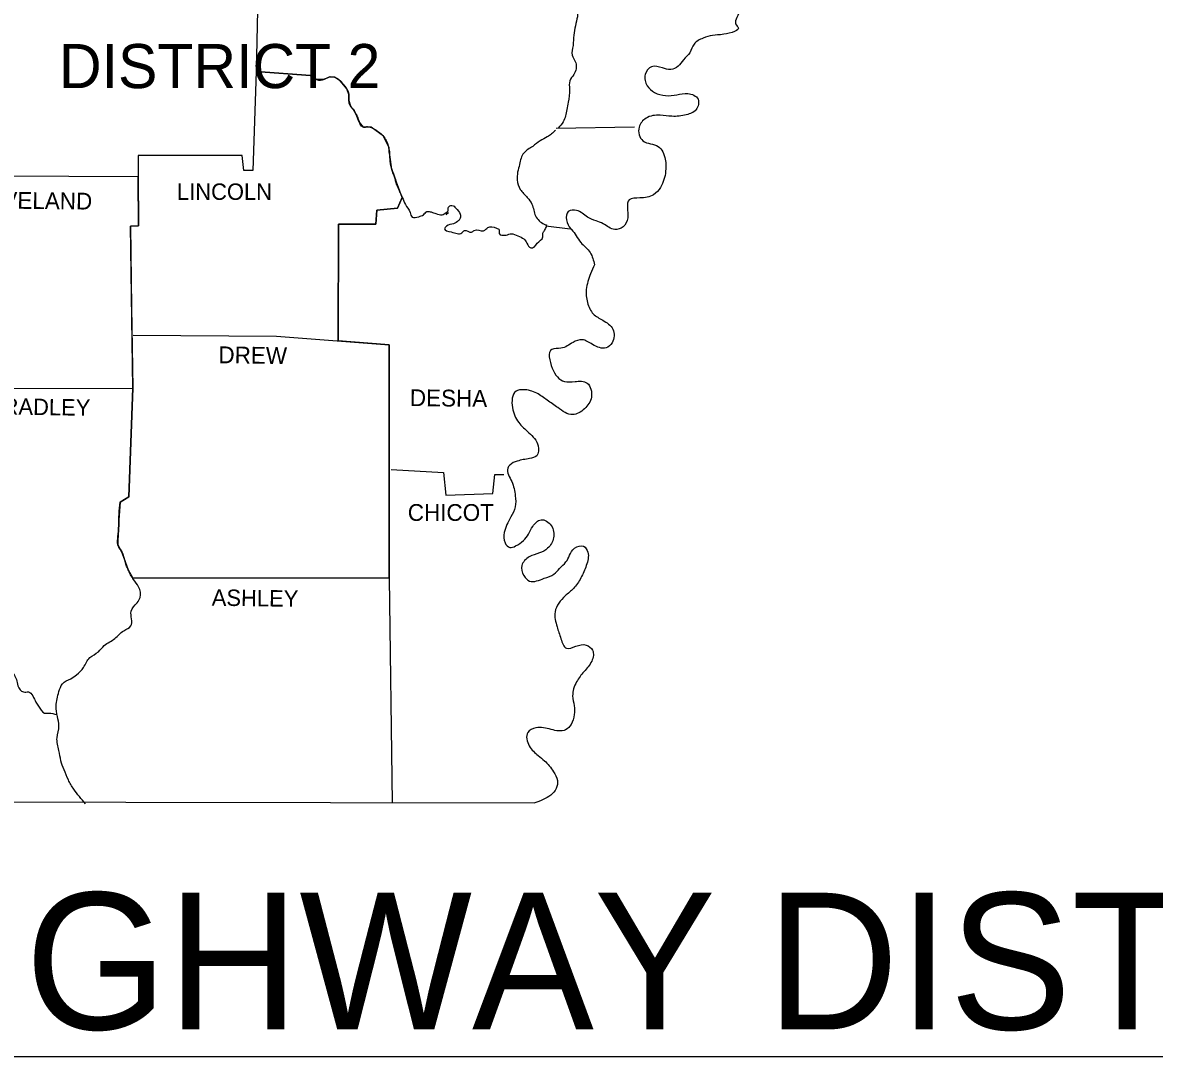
# Model space of a CAD drawing. Extents: x -33639 to 34530, y -17264 to 5867.
# Drawn here: x -16002 to -14408, y -10461 to -9004 of the extents above; entities that cross this region are included whole.
import ezdxf

# ---------------------------------------------------------------- set-up
doc = ezdxf.new("R2010")
doc.units = 0
for name, color, linetype in [('1', 7, 'Continuous'), ('2', 7, 'Continuous'), ('3', 7, 'Continuous'), ('S_MISC_BOUNDARY', 7, 'Continuous')]:
    doc.layers.add(name, color=color, linetype=linetype)

msp = doc.modelspace()

# ---------------------------------------------------------------- linework, layer by layer
at = {"layer": '1'}
for p, q in [((-15250.6, -9152.5), (-15140.6, -9150.8)), ((-17741.9, -10460.7), (-14228.8, -10460.7))]:
    msp.add_line(p, q, dxfattribs=at)
for points in [[(-15668.9, -8856.7), (-15673.3, -9072.7), (-15596.8, -9078.7)], [(-15673.3, -9072.7), (-15678.3, -9212.5), (-15690.9, -9212.5), (-15693.1, -9191), (-15839.5, -9191), (-15839.5, -9219.4)], [(-15467.5, -9250.4), (-15474.1, -9265.3), (-15503.3, -9268.1), (-15504.9, -9287.9), (-15557.2, -9287.9), (-15557.7, -9452.4)], [(-15405.8, -9274.7), (-15404.2, -9273), (-15402.5, -9271.4), (-15402.5, -9271.4)], [(-15846.9, -9444.2), (-15644.7, -9445.8), (-15486.2, -9457.9)], [(-15486.2, -9457.9), (-15486.2, -9787), (-15481.8, -10103.5)], [(-16096, -9519.6), (-15847.2, -9519)], [(-15483.4, -9633.5), (-15409.7, -9637.9), (-15406.4, -9669.8), (-15339.8, -9667.6), (-15337.1, -9640.6), (-15324.4, -9640.6)], [(-17299.1, -9655), (-17298, -10100.2), (-15280.9, -10103.5)], [(-15847.4, -9786.5), (-15486.2, -9786.5)]]:
    msp.add_lwpolyline(points, dxfattribs=at)
for points in [[(-14817.5, -8617), (-14830.2, -8632.9), (-14848.9, -8623), (-14848.9, -8609.8), (-14846.1, -8596.1), (-14852.7, -8587.3), (-14864.3, -8591.1), (-14864.3, -8608.2), (-14865.4, -8624.7), (-14868.7, -8648.4), (-14861, -8655.5), (-14843.4, -8657.7), (-14830.7, -8661), (-14823, -8673.7), (-14823.6, -8689.1), (-14829.6, -8703.9), (-14838.4, -8716), (-14852.2, -8720.5), (-14863.2, -8713.3), (-14867.6, -8699), (-14872.6, -8686.3), (-14881.9, -8677), (-14891.8, -8687.4), (-14894, -8706.7), (-14893.5, -8723.2), (-14893.5, -8745.8), (-14879.2, -8760.6), (-14870.4, -8777.7), (-14873.1, -8793.1), (-14883.6, -8811.3), (-14888, -8827.2), (-14892.4, -8848.7), (-14891.8, -8872.3), (-14895.7, -8895.5), (-14903.4, -8910.9), (-14917.7, -8923.5), (-14927, -8931.8), (-14934.7, -8940), (-14938.6, -8956.6), (-14941.3, -8968.1), (-14951.8, -8981.9), (-14960.1, -8983), (-14966.7, -8977.5), (-14968.9, -8968.1), (-14968.9, -8958.8), (-14973.3, -8949.4), (-14987, -8945.5), (-14998, -8946.1), (-15003, -8953.8), (-14995.8, -8975.3), (-14993.1, -8989), (-14996.9, -9007.7), (-14994.7, -9009.9), (-15014.5, -9020.4), (-15030.5, -9022), (-15043.7, -9025.9), (-15056.4, -9034.2), (-15062.4, -9046.3), (-15071.2, -9056.2), (-15078.9, -9065.5), (-15089.4, -9069.9), (-15101, -9067.7), (-15116.4, -9066.1), (-15125.2, -9077.1), (-15122.4, -9093), (-15112, -9102.4), (-15096.5, -9106.8), (-15080.6, -9105.7), (-15065.2, -9104), (-15050.9, -9111.8), (-15053.6, -9126.6), (-15067.4, -9133.8), (-15087.7, -9136), (-15104.3, -9134.3), (-15124.1, -9138.7), (-15134, -9151.4), (-15128.5, -9170.6), (-15107, -9178.3), (-15097.1, -9196.5), (-15096.5, -9213.6), (-15103.7, -9236.1), (-15113.6, -9246.6), (-15132.9, -9251), (-15147.7, -9253.7), (-15149.9, -9279.1), (-15156.5, -9291.7), (-15168.1, -9295.6), (-15184.6, -9287.3), (-15194.5, -9283.5), (-15206.6, -9278), (-15222, -9268.6), (-15233.6, -9270.3), (-15230.3, -9294.5), (-15229.2, -9295.6), (-15216, -9313.7), (-15202.8, -9328), (-15196.7, -9345.1)], [(-15596.8, -9078.7), (-15588.6, -9084.2), (-15577, -9083.7), (-15569.3, -9080.4), (-15563.2, -9080.9), (-15555, -9085.9), (-15549.5, -9092.5), (-15545.6, -9097.4), (-15542.9, -9105.1), (-15542.9, -9112.3), (-15540.1, -9122.2), (-15536.8, -9126.1), (-15532.4, -9133.2), (-15529.7, -9139.8), (-15528, -9144.2), (-15522, -9151.4), (-15516.5, -9150.8), (-15511.5, -9151.4), (-15504.9, -9155.2), (-15495, -9162.9), (-15493.4, -9165.1), (-15486.7, -9179.4), (-15485.6, -9188.3), (-15484.5, -9199.8), (-15482.3, -9210.8), (-15477.9, -9222.9), (-15475.7, -9231.2), (-15470.8, -9242.7), (-15467.5, -9250.4), (-15463.1, -9260.3), (-15456.5, -9271.4), (-15453.7, -9278), (-15444.4, -9277.4), (-15437.8, -9274.7), (-15432.8, -9270.3), (-15426.8, -9270.8), (-15420.2, -9273), (-15411.4, -9274.7), (-15405.8, -9271.4), (-15403.1, -9269.2), (-15402.5, -9264.2), (-15397.6, -9261.5), (-15392.1, -9265.3), (-15386, -9274.1), (-15386, -9279.6), (-15388.2, -9282.9), (-15395.4, -9287.3), (-15405.3, -9290.6), (-15408, -9294.5), (-15398.7, -9298.9), (-15383.8, -9300), (-15380, -9296.7), (-15370.1, -9299.4), (-15366.2, -9296.7), (-15353, -9297.2), (-15347, -9292.8), (-15334.9, -9293.4), (-15331, -9296.1), (-15331, -9301.1), (-15321.1, -9303.3), (-15313.9, -9301.6), (-15304.6, -9304.4), (-15296.3, -9308.8), (-15291.9, -9314.8), (-15286.4, -9321.4), (-15281.5, -9319.8), (-15277.6, -9314.8), (-15269.4, -9306), (-15269.4, -9300.5), (-15267.2, -9296.7), (-15264.4, -9291.2)], [(-15196.7, -9345.1), (-15202.2, -9357.8), (-15208.3, -9379.8), (-15206.6, -9398.5), (-15198.4, -9414.4), (-15185.2, -9423.3), (-15170.8, -9435.9), (-15171.9, -9455.2), (-15180.2, -9462.3), (-15199.5, -9457.4), (-15214.3, -9450.8), (-15227, -9454.6), (-15244, -9462.9), (-15256.7, -9464.5), (-15256.2, -9490.9), (-15239.1, -9509.7), (-15224.2, -9509.7), (-15207.2, -9511.9), (-15201.1, -9531.7), (-15211, -9548.2), (-15227.5, -9556.4), (-15248.4, -9546.5), (-15263.3, -9536.1), (-15278.2, -9526.2), (-15296.9, -9521.2), (-15307.3, -9523.4), (-15312.3, -9546.5), (-15303.5, -9567.4), (-15289.2, -9581.8), (-15276, -9600.5), (-15278.2, -9614.2), (-15288.1, -9618.1), (-15305.7, -9621.9), (-15316.1, -9627.4), (-15318.9, -9631.8), (-15313.4, -9650.6), (-15308.4, -9670.9), (-15308.4, -9686.3), (-15314.5, -9700.6), (-15323.8, -9722.6), (-15322.7, -9737), (-15316.1, -9743.6), (-15307.9, -9741.4), (-15296.9, -9733.7), (-15289.7, -9724.8), (-15283.7, -9713.8), (-15272.1, -9704.5), (-15257.8, -9712.7), (-15254.5, -9729.8), (-15262.8, -9744.7), (-15274.3, -9751.3), (-15288.6, -9756.8), (-15299.1, -9768.9), (-15296.3, -9783.2), (-15288.1, -9790.9), (-15267.7, -9787), (-15253.9, -9781), (-15246.2, -9773.3), (-15236.9, -9763.9), (-15231.9, -9754.6), (-15224.8, -9744.7), (-15212.1, -9741.9), (-15206.1, -9750.2), (-15208.3, -9768.9), (-15216, -9786.5), (-15226.4, -9801.3), (-15238, -9811.8), (-15252.3, -9834.4), (-15249.5, -9855.3), (-15244, -9872.3), (-15236.3, -9885.6), (-15223.1, -9882.8), (-15208.3, -9881.1), (-15199.5, -9888.3), (-15200.6, -9903.7), (-15211.6, -9918.6), (-15222, -9932.9), (-15227.5, -9952.7), (-15225.3, -9966.5), (-15225.3, -9979.1), (-15229.7, -9992.9), (-15237.4, -10000.6), (-15257.8, -10000), (-15279.3, -9997.8), (-15290.8, -10004.4), (-15288.6, -10023.1), (-15276, -10036.9), (-15267.2, -10044.1), (-15254.5, -10059.5), (-15249, -10072.1), (-15250.6, -10083.1), (-15258.4, -10092.5), (-15280.9, -10103.5)], [(-16413.5, -9806.9), (-16404.7, -9800.8), (-16396.5, -9797.5), (-16388.2, -9799.1), (-16379.4, -9800.2), (-16371.7, -9799.1), (-16361.8, -9800.8), (-16353.6, -9805.8), (-16344.2, -9809.6), (-16334.8, -9809.6), (-16326.6, -9809.6), (-16319.4, -9814.6), (-16306.2, -9814), (-16295.2, -9809.6), (-16284.2, -9806.3), (-16269.4, -9804.6), (-16256.1, -9814), (-16246.8, -9821.7), (-16239.1, -9830.5), (-16233.6, -9840.4), (-16227.5, -9845.9), (-16217.6, -9849.8), (-16209.9, -9851.4), (-16200.6, -9854.2), (-16195.6, -9856.4), (-16191.2, -9866.8), (-16184, -9881.1), (-16170.3, -9886.1), (-16153.2, -9879.5), (-16139.5, -9875.6), (-16129.6, -9872.3), (-16123.5, -9870.1), (-16118, -9869.6), (-16119.7, -9868.5), (-16113.1, -9866.8), (-16107, -9871.2), (-16103.1, -9877.3), (-16096.5, -9886.1), (-16090.5, -9893.8), (-16084.4, -9896.6), (-16078.4, -9893.3), (-16070.1, -9896), (-16063, -9898.8), (-16054.7, -9901), (-16047.6, -9901.5), (-16038.2, -9903.7), (-16031, -9907.6), (-16024.4, -9911.4), (-16017.8, -9918.6), (-16011.2, -9929.6), (-16009, -9938.4), (-16001.3, -9947.2), (-15994.2, -9947.2), (-15983.7, -9961.5), (-15979.9, -9967), (-15971.6, -9976.9), (-15965.6, -9976.9), (-15954, -9979.1)]]:
    msp.add_spline(points, degree=3, dxfattribs=at)
at = {"layer": 'S_MISC_BOUNDARY'}
for p, q in [((-15569.4, -9080.4), (-15573.5, -9082.2)), ((-15693.1, -9191), (-15839.5, -9191)), ((-15690.9, -9212.5), (-15693.1, -9191)), ((-15678.3, -9212.5), (-15690.9, -9212.5)), ((-15839, -9290.1), (-15850.5, -9290.6)), ((-15850.5, -9290.6), (-15848.9, -9404.8)), ((-15265.5, -9290.1), (-15230.8, -9294.5)), ((-15486.2, -9457.9), (-15557.7, -9452.5)), ((-15850, -9595.5), (-15852.7, -9672)), ((-15852.7, -9672), (-15864.8, -9679.7))]:
    msp.add_line(p, q, dxfattribs=at)
for points in [[(-15839.5, -9191), (-15839.5, -9219.4), (-15839, -9290.1), (-15850.5, -9290.6), (-15848.9, -9404.8), (-15847.2, -9519), (-15850, -9595.5), (-15852.7, -9672), (-15864.8, -9679.7), (-15866.8, -9704.8), (-15868.1, -9733.9), (-15868.1, -9739.7), (-15864.8, -9746), (-15862.9, -9749.7), (-15857.7, -9764.5), (-15855.8, -9769.7), (-15853.8, -9774.9), (-15850, -9781.8), (-15847.3, -9786.6), (-15666.8, -9786.5), (-15486.2, -9787), (-15486.2, -9457.9), (-15557.7, -9452.4), (-15557.2, -9287.9), (-15504.9, -9287.9), (-15503.3, -9268.1), (-15474.1, -9265.3), (-15467.5, -9250.4), (-15482.3, -9210.8), (-15486.7, -9179.4), (-15494.2, -9164), (-15511.5, -9151.4), (-15516.5, -9150.8), (-15522, -9151.4), (-15528, -9144.2), (-15532.4, -9133.2), (-15536.8, -9126.1), (-15540.1, -9122.2), (-15542.9, -9112.3), (-15542.9, -9105.1), (-15545.6, -9097.4), (-15555, -9085.9), (-15563.1, -9081), (-15569.3, -9080.3), (-15577.1, -9083.7), (-15588.5, -9084.2), (-15596.9, -9078.7), (-15673.3, -9072.7), (-15678.3, -9212.5), (-15690.9, -9212.5), (-15693.1, -9191), (-15839.5, -9191)], [(-15596.8, -9078.7), (-15673.3, -9072.7), (-15678.3, -9212.5)], [(-15555, -9085.8), (-15563.1, -9081), (-15569.2, -9080.4)], [(-15542.9, -9109.2), (-15542.9, -9105.1), (-15545.6, -9097.4), (-15554.7, -9086.2)], [(-15528.1, -9144), (-15532.4, -9133.2), (-15536.8, -9126.1), (-15538.1, -9124.6)], [(-15486.1, -9184), (-15486.7, -9179.4), (-15494.2, -9164), (-15511.5, -9151.4), (-15516.5, -9150.8), (-15517.8, -9151)], [(-15839.5, -9191), (-15839.5, -9219.4), (-15839.5, -9221.3), (-15839, -9290.1)], [(-15864.8, -9679.7), (-15852.7, -9672), (-15847.2, -9519), (-15850.5, -9290.6), (-15839, -9290.1), (-15839.5, -9221.3), (-15839.5, -9221.3), (-16035.5, -9220.2), (-16115.8, -9225.1)], [(-15557.7, -9452.4), (-15557.2, -9287.9), (-15504.9, -9287.9), (-15503.3, -9268.1), (-15474.1, -9265.3), (-15467.5, -9250.4)], [(-15848.9, -9404.8), (-15847.2, -9519), (-15850, -9595.5)], [(-15557.7, -9452.5), (-15557.7, -9452.4)], [(-15857.7, -9764.5), (-15855.8, -9769.7), (-15853.8, -9774.9), (-15850, -9781.8), (-15847.4, -9786.5), (-15666.8, -9786.5), (-15486.2, -9787), (-15486.2, -9457.9)], [(-15864.8, -9679.7), (-15866.8, -9704.8), (-15866.8, -9705.8)], [(-15867.4, -9718.5), (-15868.1, -9733.9), (-15868.1, -9739.7), (-15864.8, -9746), (-15863.7, -9748.3)]]:
    msp.add_lwpolyline(points, dxfattribs=at)
for points in [[(-15387.7, -8794.2), (-15386, -8816.8), (-15372.8, -8820.1), (-15367.3, -8826.1), (-15364.6, -8838.8), (-15355.2, -8844.3), (-15342.6, -8852), (-15334.9, -8857.5), (-15329.3, -8866.3), (-15326, -8880.6), (-15317.2, -8890), (-15305.1, -8894.4), (-15296.3, -8904.8), (-15290.8, -8919.7), (-15282, -8926.3), (-15273.2, -8937.8), (-15268.8, -8942.8), (-15261.1, -8956), (-15253.4, -8962.6), (-15247.9, -8966.5), (-15239.1, -8969.2), (-15228.1, -8976.4), (-15220.9, -8987.4), (-15220.9, -8995.6), (-15223.7, -9008.3), (-15225.9, -9021.5), (-15227, -9036.4), (-15228.1, -9049.6), (-15223.1, -9060.6), (-15225.9, -9077.1), (-15231.4, -9085.9), (-15231.9, -9098), (-15233.6, -9116.2), (-15235.8, -9126.6), (-15240.7, -9143.7), (-15247.9, -9152.5)], [(-15251.7, -9155.8), (-15263.3, -9165.1), (-15273.2, -9170.6), (-15283.7, -9178.3), (-15296.3, -9187.7), (-15302.4, -9203.7), (-15305.7, -9225.7), (-15301.3, -9238.9), (-15291.4, -9250.4), (-15284.8, -9259.8), (-15279.8, -9276.3), (-15267.7, -9287.9), (-15263.9, -9289.5)], [(-15484.6, -9199.8), (-15485.6, -9188.3), (-15486.1, -9184)], [(-15196.7, -9345.1), (-15202.2, -9357.8), (-15208.3, -9379.8), (-15206.6, -9398.5), (-15198.4, -9414.4), (-15185.2, -9423.3), (-15170.8, -9435.9), (-15171.9, -9455.2), (-15180.2, -9462.3), (-15199.5, -9457.4), (-15214.3, -9450.8), (-15227, -9454.6), (-15244, -9462.9), (-15256.7, -9464.5), (-15256.2, -9490.9), (-15239.1, -9509.7), (-15224.2, -9509.7), (-15207.2, -9511.9), (-15201.1, -9531.7), (-15211, -9548.2), (-15227.5, -9556.4), (-15248.4, -9546.5), (-15263.3, -9536.1), (-15278.2, -9526.2), (-15296.9, -9521.2), (-15307.3, -9523.4), (-15312.3, -9546.5), (-15303.5, -9567.4), (-15289.2, -9581.8), (-15276, -9600.5), (-15278.2, -9614.2), (-15288.1, -9618.1), (-15305.7, -9621.9), (-15316.1, -9627.4), (-15318.9, -9631.8), (-15313.4, -9650.6), (-15308.4, -9670.9), (-15308.4, -9686.3), (-15314.5, -9700.6), (-15323.8, -9722.6), (-15322.7, -9737), (-15316.1, -9743.6), (-15307.9, -9741.4), (-15296.9, -9733.7), (-15289.7, -9724.8), (-15283.7, -9713.8), (-15272.1, -9704.5), (-15257.8, -9712.7), (-15254.5, -9729.8), (-15262.8, -9744.7), (-15274.3, -9751.3), (-15288.6, -9756.8), (-15299.1, -9768.9), (-15296.3, -9783.2), (-15288.1, -9790.9), (-15267.7, -9787), (-15253.9, -9781), (-15246.2, -9773.3), (-15236.9, -9763.9), (-15231.9, -9754.6), (-15224.8, -9744.7), (-15212.1, -9741.9), (-15206.1, -9750.2), (-15208.3, -9768.9), (-15216, -9786.5), (-15226.4, -9801.3), (-15238, -9811.8), (-15252.3, -9834.4), (-15249.5, -9855.3), (-15244, -9872.3), (-15236.3, -9885.6), (-15223.1, -9882.8), (-15208.3, -9881.1), (-15199.5, -9888.3), (-15200.6, -9903.7), (-15211.6, -9918.6), (-15222, -9932.9), (-15227.5, -9952.7), (-15225.3, -9966.5), (-15225.3, -9979.1), (-15229.7, -9992.9), (-15237.4, -10000.6), (-15257.8, -10000), (-15279.3, -9997.8), (-15290.8, -10004.4), (-15288.6, -10023.1), (-15276, -10036.9), (-15267.2, -10044.1), (-15254.5, -10059.5), (-15249, -10072.1), (-15250.6, -10083.1), (-15258.4, -10092.5), (-15280.9, -10103.5)], [(-15913.8, -10104.6), (-15930.3, -10084.2), (-15938, -10071), (-15944.1, -10056.7), (-15948.5, -10044.1), (-15951.2, -10029.7), (-15954, -10011.6), (-15951.2, -9995.1), (-15953.4, -9981.9), (-15955.1, -9967), (-15951.2, -9946.6), (-15946.3, -9935.6), (-15934.7, -9928.5), (-15926.5, -9923), (-15916.6, -9912.5), (-15907.8, -9898.8), (-15895.7, -9890.5), (-15887.4, -9881.7), (-15879.7, -9876.7), (-15872.5, -9871.8), (-15859.9, -9860.8), (-15850, -9854.2), (-15849.4, -9833.3), (-15841.2, -9821.7), (-15836.8, -9814), (-15839, -9799.1), (-15846.1, -9788.7), (-15853.8, -9774.9), (-15857.7, -9764.5), (-15861.5, -9752.4), (-15868.1, -9739.7), (-15868.1, -9728.2), (-15867, -9712.7), (-15866.5, -9696.8), (-15864.8, -9679.7)], [(-15866.8, -9705.8), (-15867, -9712.7), (-15867.4, -9718.5)]]:
    msp.add_spline(points, degree=3, dxfattribs=at)
for points in [[(-15573.5, -9082.2), (-15574.7, -9082.8), (-15575.8, -9083.4), (-15577, -9083.7), (-15580.6, -9084.6), (-15584.9, -9085.4), (-15588.6, -9084.2), (-15591.7, -9083.2), (-15594.5, -9081.3), (-15596.8, -9078.7)], [(-15569.2, -9080.4), (-15569.2, -9080.4), (-15569.3, -9080.4), (-15569.3, -9080.4), (-15569.3, -9080.4), (-15569.4, -9080.4), (-15569.4, -9080.4)], [(-15554.7, -9086.2), (-15554.8, -9086.1), (-15554.9, -9086), (-15555, -9085.9), (-15555, -9085.9), (-15555, -9085.9), (-15555, -9085.8)], [(-15538.1, -9124.6), (-15538.8, -9123.9), (-15539.6, -9123.2), (-15540.1, -9122.2), (-15541.9, -9119.1), (-15542.5, -9115.7), (-15542.9, -9112.3), (-15543, -9111.3), (-15543, -9110.3), (-15542.9, -9109.2)], [(-15517.8, -9151), (-15519.2, -9151.3), (-15520.6, -9151.9), (-15522, -9151.4), (-15525.1, -9150.2), (-15526.8, -9147.1), (-15528, -9144.2), (-15528.1, -9144.2), (-15528.1, -9144.1), (-15528.1, -9144)], [(-15467.5, -9250.4), (-15468.6, -9247.9), (-15469.7, -9245.3), (-15470.8, -9242.7), (-15472.4, -9238.9), (-15474.1, -9235), (-15475.7, -9231.2), (-15476.9, -9228.6), (-15477.1, -9225.6), (-15477.9, -9222.9), (-15479.2, -9218.8), (-15481.2, -9215), (-15482.3, -9210.8), (-15483.4, -9207.2), (-15484.1, -9203.5), (-15484.5, -9199.8), (-15484.5, -9199.8), (-15484.6, -9199.8), (-15484.6, -9199.8)], [(-15863.7, -9748.3), (-15862.8, -9749.6), (-15862, -9750.9), (-15861.5, -9752.4), (-15860.2, -9756.4), (-15859.1, -9760.5), (-15857.7, -9764.5)]]:
    msp.add_open_spline(points, degree=3, dxfattribs=at)

# ---------------------------------------------------------------- texts
at = {"layer": '2'}
for s, height, p in [('LINCOLN', 23.11, (-15785, -9253.7)), ('CHICOT', 23.67, (-15459.8, -9706.1)), ('ARKANSAS HIGHWAY DISTRICT 2', 192.623, (-17730.9, -10422.7))]:
    msp.add_text(s, height=height, dxfattribs=at).set_placement(p)
for s, height, rotation, p in [('CLEVELAND', 23.67, 359.3377, (-16092.7, -9265.3)), ('DREW', 23.66, 359.2258, (-15726.7, -9483.8)), ('BRADLEY', 23.11, 359.1449, (-16051.4, -9555.9)), ('DESHA', 23.66, 359.3704, (-15457, -9544.3)), ('ASHLEY', 23.11, 359.2361, (-15736.1, -9825.6))]:
    msp.add_text(s, height=height, rotation=rotation, dxfattribs=at).set_placement(p)
at = {"layer": '3'}
msp.add_text('DISTRICT 2', height=62.19, dxfattribs=at).set_placement((-15951.2, -9096.3))

doc.saveas('drawing.dxf')
